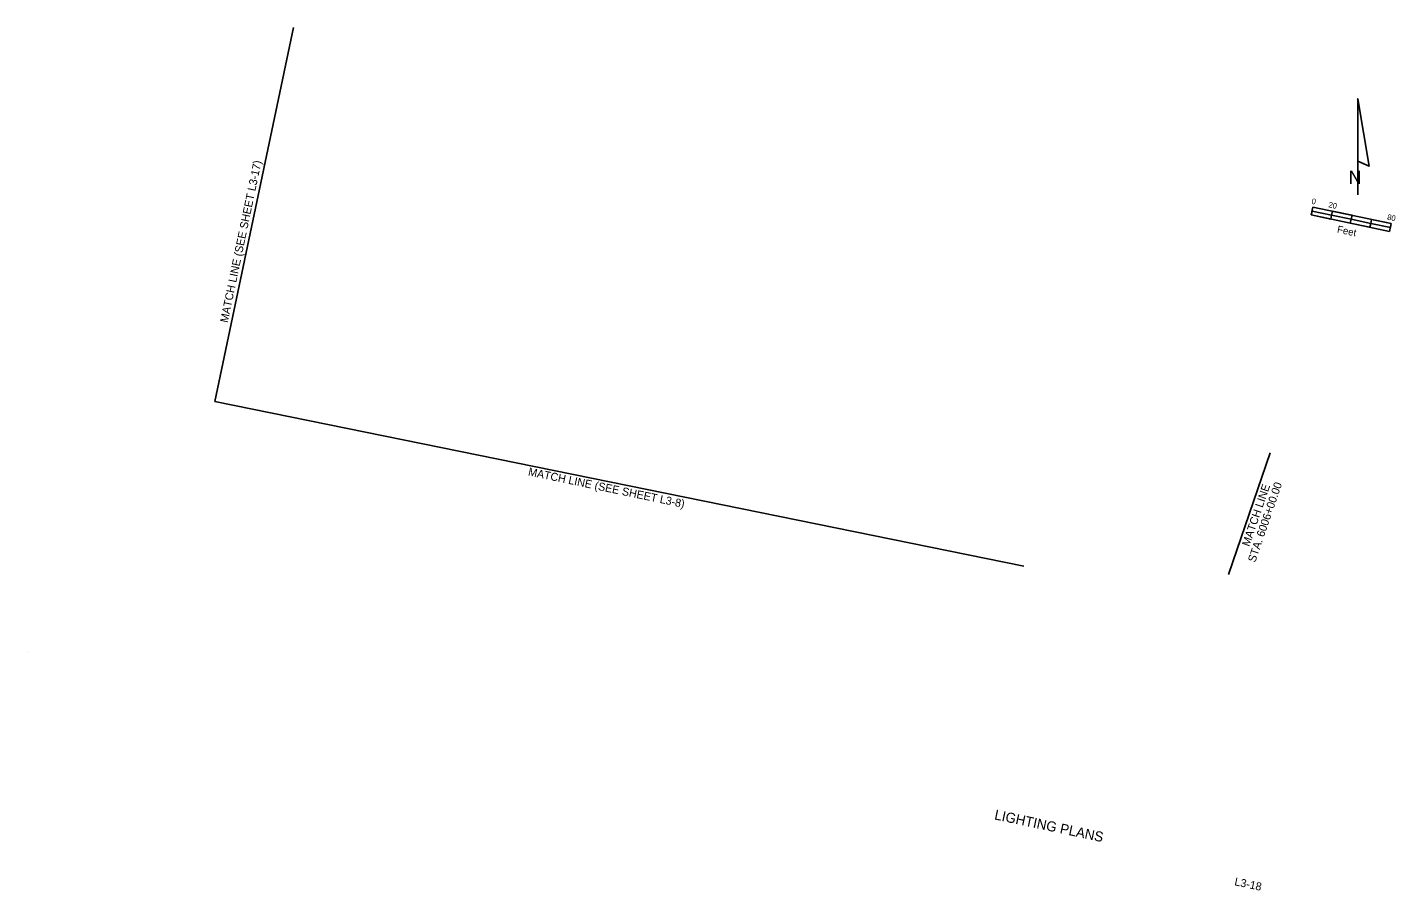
# Model space of a CAD drawing. Extents: x 918394 to 919761, y 636942 to 637804.
import ezdxf

# ---------------------------------------------------------------- set-up
doc = ezdxf.new("R2010")
doc.units = 0
for name, color, linetype in [('CGBack_ep', 7, 'Continuous'), ('CGFace_ep', 7, 'Continuous'), ('ConcSlabs_ep', 7, 'Continuous'), ('PavtConcJoints_ep', 7, 'Continuous'), ('SignMulti_ep', 7, 'Continuous'), ('Slopes_ep', 7, 'Continuous')]:
    doc.layers.add(name, color=color, linetype=linetype)

msp = doc.modelspace()

# ---------------------------------------------------------------- linework, layer by layer
at = {"layer": 'CGBack_ep'}
for p, q in [((918580.9, 637430.3), (918659.6, 637804.2)), ((919389.5, 637265.7), (918580.9, 637430.3)), ((919594.1, 637257.5), (919635.7, 637379))]:
    msp.add_line(p, q, dxfattribs=at)
at = {"layer": 'CGFace_ep'}
msp.add_line((919723.3, 637636.8), (919723.3, 637732.8), dxfattribs=at)
msp.add_lwpolyline([(919723.3, 637670.4), (919723.3, 637732.8), (919734.8, 637665.6)], close=True, dxfattribs=at)
at = {"layer": 'ConcSlabs_ep'}
for p, q in [((919678.4, 637624.6), (919676.8, 637616.8)), ((919756.7, 637608.1), (919678.4, 637624.6)), ((919676.8, 637616.8), (919755.1, 637600.3)), ((919755.1, 637600.3), (919756.7, 637608.1))]:
    msp.add_line(p, q, dxfattribs=at)
for points in [[(919676.8, 637616.8), (919677.6, 637620.7), (919697.2, 637616.6), (919696.3, 637612.7)], [(919697.2, 637616.6), (919698, 637620.5), (919717.6, 637616.4), (919716.7, 637612.5)], [(919715.9, 637608.6), (919716.7, 637612.5), (919736.3, 637608.3), (919735.5, 637604.4)], [(919736.3, 637608.3), (919737.1, 637612.3), (919756.7, 637608.1), (919755.9, 637604.2)]]:
    msp.add_lwpolyline(points, close=True, dxfattribs=at)
at = {"layer": 'PavtConcJoints_ep'}
msp.add_line((918393.6, 637180.8), (918393.6, 637180.8), dxfattribs=at)

# ---------------------------------------------------------------- texts
at = {"layer": 'CGBack_ep'}
for s, rotation, p in [('MATCH LINE (SEE SHEET L3-17) ', 78.1832, (918593.9, 637508.6)), ('MATCH LINE (SEE SHEET L3-8) ', 348.1832, (918893.7, 637356.6)), ('STA. 6006+00.00', 71.1342, (919620.8, 637269)), ('MATCH LINE', 71.1342, (919614.9, 637284.9))]:
    msp.add_text(s, height=8, rotation=rotation, dxfattribs=at).set_placement(p)
at = {"layer": 'CGFace_ep'}
msp.add_text('N', height=13.4, dxfattribs=at).set_placement((919714.2, 637647.7))
at = {"layer": 'ConcSlabs_ep'}
for s, height, p in [('0', 5.6, (919676.8, 637628)), ('20', 5.6, (919693.7, 637624.5)), ('80', 5.6, (919752.4, 637612.1)), ('Feet', 7.2, (919702.2, 637599.2))]:
    msp.add_text(s, height=height, rotation=348.1121, dxfattribs=at).set_placement(p)
at = {"layer": 'SignMulti_ep'}
msp.add_text('        LIGHTING PLANS         ', height=10, rotation=348.0722, dxfattribs=at).set_placement((919330.5, 637019))
at = {"layer": 'Slopes_ep'}
msp.add_text('L3-18 ', height=8, rotation=348.0722, dxfattribs=at).set_placement((919599.6, 636947))

doc.saveas('drawing.dxf')
